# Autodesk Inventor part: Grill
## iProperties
Created: 2006-03
Part Number: Grill
Document SubType Name: Modeling
Designer: t_munrn
Density: 1 g/cm^3
Author: t_munrn
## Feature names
1. Loft4
2. Loft2
3. Extrusion1
4. Split3
5. Split4
6. Shell1
